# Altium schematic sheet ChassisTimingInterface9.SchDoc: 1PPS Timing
size B; Author: M. Pirello; Organization: LIGO Laboratory; Address1: California Institute of Technology; Address2: Massachusetts Institute of Technology; Address3: National Science Foundation; Address4: Australia 2086; DocumentNumber: 9; SheetNumber: 9; SheetTotal: 12; Size: B
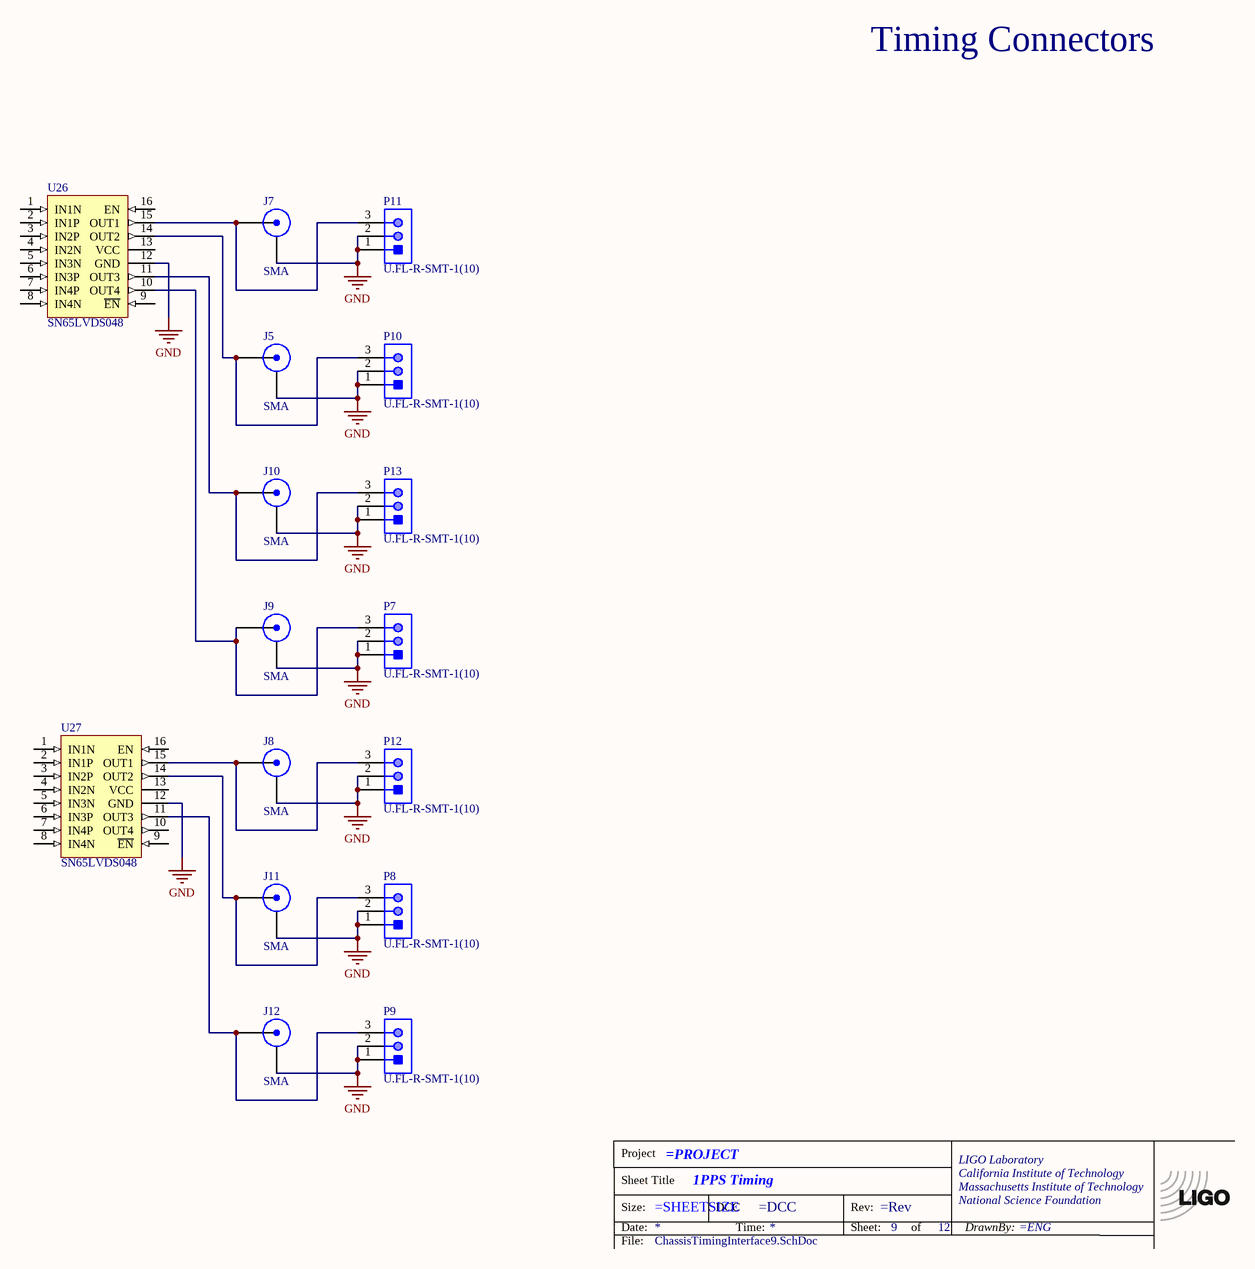
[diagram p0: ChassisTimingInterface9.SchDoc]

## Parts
*?  TitleBlock  (value not drawn)  (graphical)
?  (no value)  (no BOM)
J5  SMA  [SMA_EDGE]
J7  SMA  [SMA_EDGE]
J8  SMA  [SMA_EDGE]
J9  SMA  [SMA_EDGE]
J10  SMA  [SMA_EDGE]
J11  SMA  [SMA_EDGE]
J12  SMA  [SMA_EDGE]
P7  U.FL-R-SMT-1(10)  [HRS-U.FL-R-SMT-1(10)_V]
P8  U.FL-R-SMT-1(10)  [HRS-U.FL-R-SMT-1(10)_V]
P9  U.FL-R-SMT-1(10)  [HRS-U.FL-R-SMT-1(10)_V]
P10  U.FL-R-SMT-1(10)  [HRS-U.FL-R-SMT-1(10)_V]
P11  U.FL-R-SMT-1(10)  [HRS-U.FL-R-SMT-1(10)_V]
P12  U.FL-R-SMT-1(10)  [HRS-U.FL-R-SMT-1(10)_V]
P13  U.FL-R-SMT-1(10)  [HRS-U.FL-R-SMT-1(10)_V]
U26  SN65LVDS048  [SO-G16]
U27  SN65LVDS048  [SO-G16]

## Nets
GND: J5.2(Y) J7.2(Y) J8.2(Y) J9.2(Y) J10.2(Y) J11.2(Y) J12.2(Y) P7.1 P7.2 P8.1 P8.2 P9.1 P9.2 P10.1 P10.2 P11.1 P11.2 P12.1 P12.2 P13.1 P13.2 U26.12(GND) U27.12(GND)
NetJ5_1: J5.1(X) P10.3 U26.14(OUT2)
NetJ7_1: J7.1(X) P11.3 U26.15(OUT1)
NetJ8_1: J8.1(X) P12.3 U27.15(OUT1)
NetJ9_1: J9.1(X) P7.3 U26.10(OUT4)
NetJ10_1: J10.1(X) P13.3 U26.11(OUT3)
NetJ11_1: J11.1(X) P8.3 U27.14(OUT2)
NetJ12_1: J12.1(X) P9.3 U27.11(OUT3)

Not connected (* = marked no-connect by the designer): U26 1(IN1N) 2(IN1P) 3(IN2P) 4(IN2N) 5(IN3N) 6(IN3P) 7(IN4P) 8(IN4N) 9(~{EN}) 13(VCC) 16(EN); U27 1(IN1N) 2(IN1P) 3(IN2P) 4(IN2N) 5(IN3N) 6(IN3P) 7(IN4P) 8(IN4N) 9(~{EN}) 10(OUT4) 13(VCC) 16(EN)

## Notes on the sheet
- Timing Connectors

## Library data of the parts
? = LIGO_logo: LIGO logo
J5 J7-J12 = SMA: SMA, PCB Mount, Right Angle
P7-P13 = CMP-2000-05152-1: Ultra Small Surface Mount Coaxial Connector, -40 to 90 degC, 2-Pin SMT, RoHS, Tape and Reel; Manufacturer: Hirose Electric; Connector Style: U.FL,UltraMiniatureCoaxial; Center Contact Plating: Gold; Body Material: PhosphorBronze; Center Contact Material: Brass; Body Finish: Silver; Frequency - Max: 6GHz; Shield Termination: Solder; Impedance: 50Ohm; Online Catalog: UMCC(UltraMiniatureCoaxConnectors),U.FLSeries; Other Names: H11891TRQ5400621U.FL-R-SMT-110U.FL-R-SMT-1(10)-NDUFLRSMT110; Featured Product: U.FLSeriesConnectors; Connector Type: Receptacle,MalePin; Dielectric Material: LiquidCrystalPolymer(LCP)
U26 U27 = SN65LVDS048: LVDS RCVR; Part Number: 296-6911-5-ND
